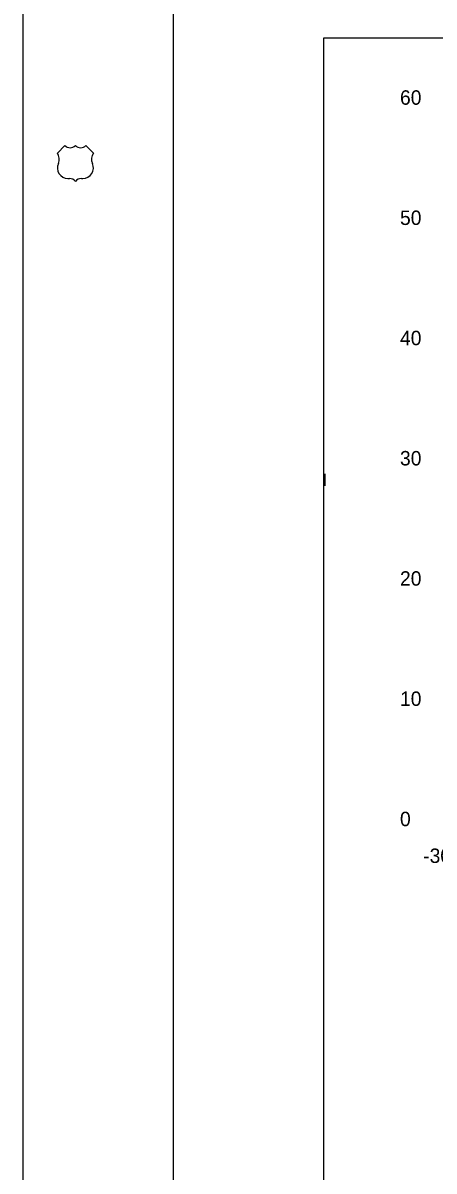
# Model space of a CAD drawing. Extents: x 1797809 to 2198143, y 249608 to 1237864.
# Drawn here: x 2195203.8 to 2195238, y 1237228.8 to 1237324.3 of the extents above; entities that cross this region are included whole.
import ezdxf

# ---------------------------------------------------------------- set-up
doc = ezdxf.new("R2010")
doc.units = 0
for name, color, linetype in [('10', 7, 'Continuous'), ('31', 7, 'Continuous'), ('GSCOLORFILL', 7, 'Continuous'), ('GSOUTLINE', 7, 'Continuous'), ('GSSHT', 7, 'Continuous'), ('Level 45', 7, 'Continuous'), ('OHUT', 7, 'Continuous'), ('PIPETEXT', 7, 'Continuous')]:
    doc.layers.add(name, color=color, linetype=linetype)

msp = doc.modelspace()

# ---------------------------------------------------------------- linework, layer by layer
at = {"layer": 'GSCOLORFILL'}
msp.add_lwpolyline([(2195216.286, 1237123.036), (2195538.786, 1237123.036), (2195538.786, 1237333.036), (2195216.286, 1237333.036)], close=True, dxfattribs=at)
at = {"layer": 'GSOUTLINE'}
for points in [[(2195207.272, 1237314.113), (2195206.648, 1237313.49)], [(2195209.647, 1237313.49), (2195209.022, 1237314.113)], [(2195207.522, 1237311.372), (2195207.647, 1237311.372)], [(2195208.647, 1237311.372), (2195208.772, 1237311.372)]]:
    msp.add_lwpolyline(points, dxfattribs=at)
for centre, major_axis, start_param, end_param in [((2195205.937, 1237312.981), (0.875, 0), 5.853097, 6.905662), ((2195207.71, 1237314.558), (0.625, 0), 3.936991, 5.487786), ((2195208.584, 1237314.558), (0.625, 0), 3.936991, 5.487786), ((2195210.357, 1237312.981), (0.875, 0), 2.519116, 3.571681), ((2195207.522, 1237312.244), (0.875, 0), 2.698682, 4.712389), ((2195208.772, 1237312.244), (0.875, 0), 4.712389, 6.726096), ((2195207.647, 1237310.749), (0.625, 0), 0.643501, 1.570796), ((2195208.647, 1237310.749), (0.625, 0), 1.570796, 2.498092)]:
    msp.add_ellipse(centre, major_axis=major_axis, ratio=0.997059, start_param=start_param, end_param=end_param, dxfattribs=at)
at = {"layer": 'GSSHT'}
msp.add_lwpolyline([(2195203.786, 1237118.036), (2195543.786, 1237118.036), (2195543.786, 1237338.036), (2195203.786, 1237338.036)], close=True, dxfattribs=at)
at = {"layer": 'Level 45'}
msp.add_lwpolyline([(2195228.783, 1237133.046), (2195528.783, 1237133.046), (2195528.783, 1237323.046), (2195228.783, 1237323.046)], close=True, dxfattribs=at)
at = {"layer": 'OHUT'}
msp.add_line((2195228.783, 1237243.036), (2195228.783, 1237243.046), dxfattribs=at)
at = {"layer": 'PIPETEXT'}
msp.add_lwpolyline([(2195228.898, 1237286.82), (2195228.885, 1237285.82)], dxfattribs=at)
msp.add_lwpolyline([(2195228.898, 1237286.82), (2195228.885, 1237285.82)], dxfattribs=at)

# ---------------------------------------------------------------- texts
at = {"layer": '10'}
msp.add_text('-30', height=1.2, dxfattribs=at).set_placement((2195237.08, 1237254.446))
at = {"layer": '31'}
for s, p in [('60', (2195235.15, 1237317.506)), ('50', (2195235.15, 1237307.506)), ('40', (2195235.15, 1237297.506)), ('30', (2195235.15, 1237287.506)), ('20', (2195235.15, 1237277.506)), ('10', (2195235.15, 1237267.506)), ('0', (2195235.15, 1237257.506))]:
    msp.add_text(s, height=1.2, dxfattribs=at).set_placement(p)

doc.saveas('drawing.dxf')
